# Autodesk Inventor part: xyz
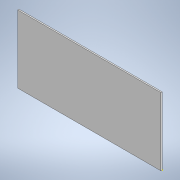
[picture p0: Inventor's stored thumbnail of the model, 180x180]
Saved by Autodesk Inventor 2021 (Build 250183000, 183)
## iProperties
Created: 2021-07
Part Number: xyz
Material: Generic
Document SubType Name: Modeling
Designer: CHIRAG
Density: 1 g/cm^3
Appearance: Default
Author: CHIRAG
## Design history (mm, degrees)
sketch "Sketch7"
  geometry: 1 further point
sketch "Sketch8"
  geometry: 1 further point
sketch "Sketch9"
  geometry: L1 (0, 0)-(-550, 0); L2 (-550, 0)-(-550, 260); L3 (-550, 260)-(0, 260); L4 (0, 260)-(0, 0)
  constraints: 8 end point, 2 parallel, 1 horizontal, 1 perpendicular
  dimensions: "d22" = 550 distance of L2.end L3.end; "d23" = 260 distance of L1.end L2.end
extrude "Extrusion6" new body sketch "Sketch9" distance "d24" = 5; taper "d25" = 0 deg
body "Solid2"
